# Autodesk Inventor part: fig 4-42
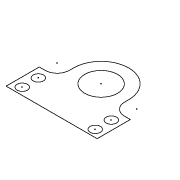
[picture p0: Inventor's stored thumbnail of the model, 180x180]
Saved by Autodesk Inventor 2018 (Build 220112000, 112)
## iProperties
Created: 2004-05
Part Number: fig 4-42
Document SubType Name: Modeling
Designer: CADCIM Technologies
Manufacturer: Standard
Standards Organization: Custom
Density: 1 g/cm^3
Material: Generic
Appearance: Default
Author: CADCIM Technologies
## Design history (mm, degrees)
sketch "Sketch1"
  geometry: L1 (41.331, 50.432)-(41.331, 48.38); L2 (35.331, 42.38)-(32.489, 42.38); L3 (32.489, 42.38)-(32.489, 26.047); L4 (68.481, 50.432)-(68.481, 48.38); L5 (74.481, 42.38)-(77.323, 42.38); L6 (77.323, 42.38)-(77.323, 26.047); L7 (32.489, 26.047)-(77.323, 26.047); C1 r 8.09 at (54.906, 50.432); C2 r 2.534 at (36.931, 29.558); C3 r 2.534 at (36.931, 37.474); C4 r 2.534 at (72.881, 37.474); C5 r 2.534 at (72.881, 29.558); A1 r 13.575 centre (54.906, 50.432) between (68.481, 50.432) and (41.331, 50.432); A2 r 6 centre (35.331, 48.38) between (35.331, 42.38) and (41.331, 48.38); A3 r 6 centre (74.481, 48.38) between (68.481, 48.38) and (74.481, 42.38)
  constraints: 14 end point, 8 centre point, 6 point on circle, 6 tangent, 3 equal length, 2 horizontal, 2 perpendicular, 1 coincident, 1 equal radius, 1 parallel, 1 vertical
